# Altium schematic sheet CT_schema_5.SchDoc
size 258 x 142 mm
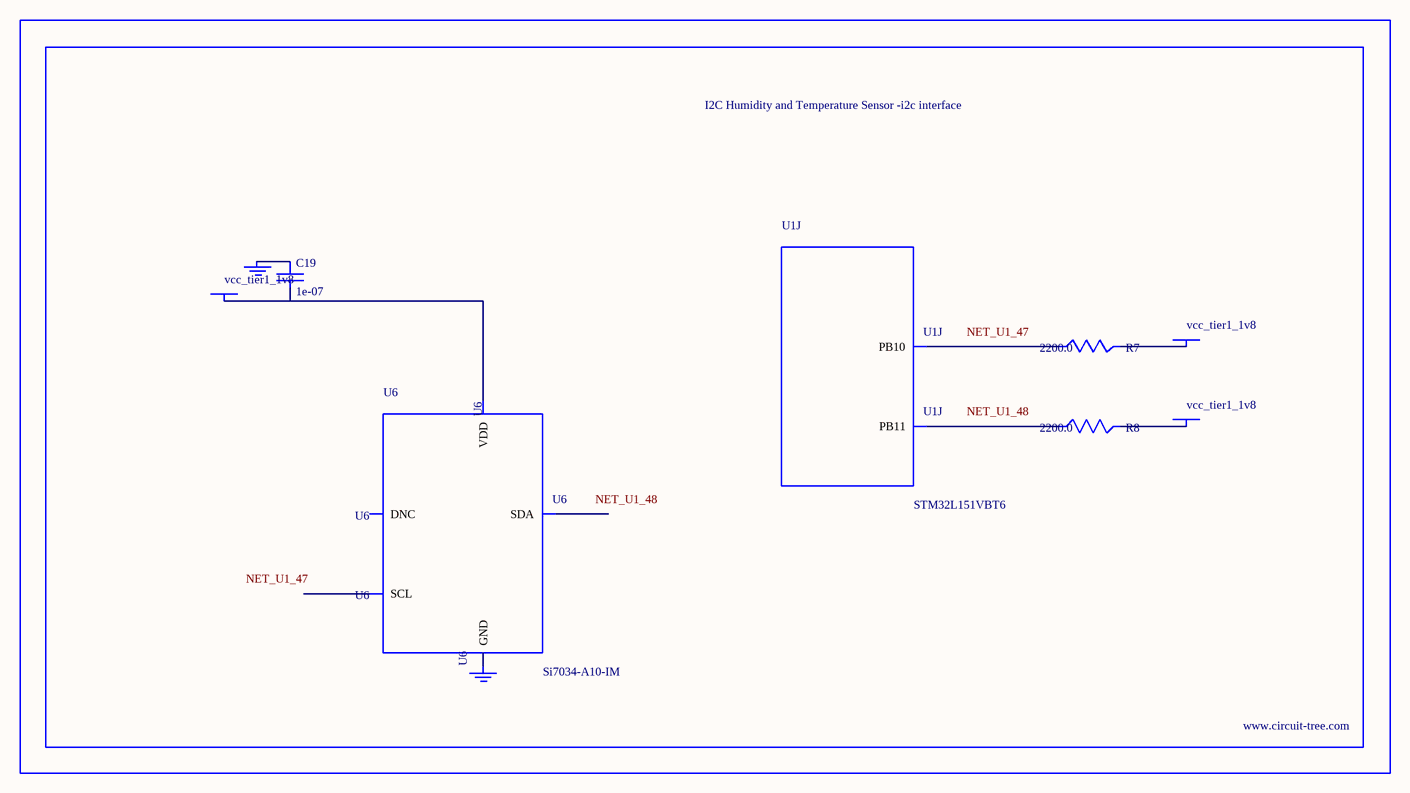
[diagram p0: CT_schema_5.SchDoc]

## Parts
BORDER4  (no value)
C19  1e-07  [C0402]
GND_INSTANCE_4_0  (no value)
GND_INSTANCE_4_1  (no value)
POWER_INSTANCE_4_0  vcc_tier1_1v8
POWER_INSTANCE_4_1  vcc_tier1_1v8
POWER_INSTANCE_4_2  vcc_tier1_1v8
R7  2200.0  [R0603]
R8  2200.0  [R0603]
U1  STM32L151VBT6  [LQFP100]  (part J of 11)
U6  Si7034-A10-IM  [SI7034-A10-IM]

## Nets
NetC19_1: C19.1 GND_INSTANCE_4_0.0(GND)
NetC19_2: C19.2 POWER_INSTANCE_4_0.0(PWR) U6.1(VDD)
NetGND_INSTANCE_4_1_0: GND_INSTANCE_4_1.0(GND) U6.5(GND)
NetPOWER_INSTANCE_4_1_0: POWER_INSTANCE_4_1.0(PWR) R7.2
NetPOWER_INSTANCE_4_2_0: POWER_INSTANCE_4_2.0(PWR) R8.2
NetR7_1: R7.1 U1.47(PB10)
NetR8_1: R8.1 U1.48(PB11)

Not connected (* = marked no-connect by the designer): U6 2(SCL) 3(DNC) 4(SDA)

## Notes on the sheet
- Labels drawn without touching a wire or pin: NET_U1_47, NET_U1_48

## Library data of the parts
BORDER4 = BORDER_PAGE4
C19 = C0402C104K3RACTU
GND_INSTANCE_4_0 GND_INSTANCE_4_1 = GND
POWER_INSTANCE_4_0-POWER_INSTANCE_4_2 = PWR
R7 R8 = RC0603JR-072K2L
